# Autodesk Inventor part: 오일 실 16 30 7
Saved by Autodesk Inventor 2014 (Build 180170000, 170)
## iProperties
Created: 2026-09
Part Number: 오일 실 16 30 7
Material: 고무
Document SubType Name: Modeling
Designer: dg
Density: 0.93 g/cm^3
Appearance: 고무 - 검은색 - 버전 1.1
Mass: 1.92838 g
Surface Area: 27.7342 cm^2
Volume: 2.07352 cm^3
Author: jhkim
Description: 오일-실
Creation Date: 2026-08-26
Sending System: Autodesk Inventor 2027
Preprocessor: ST-DEVELOPER v20.1
Author: dg
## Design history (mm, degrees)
node "오일 실 16 30 71"
body "Solid1"
node "기준1"
